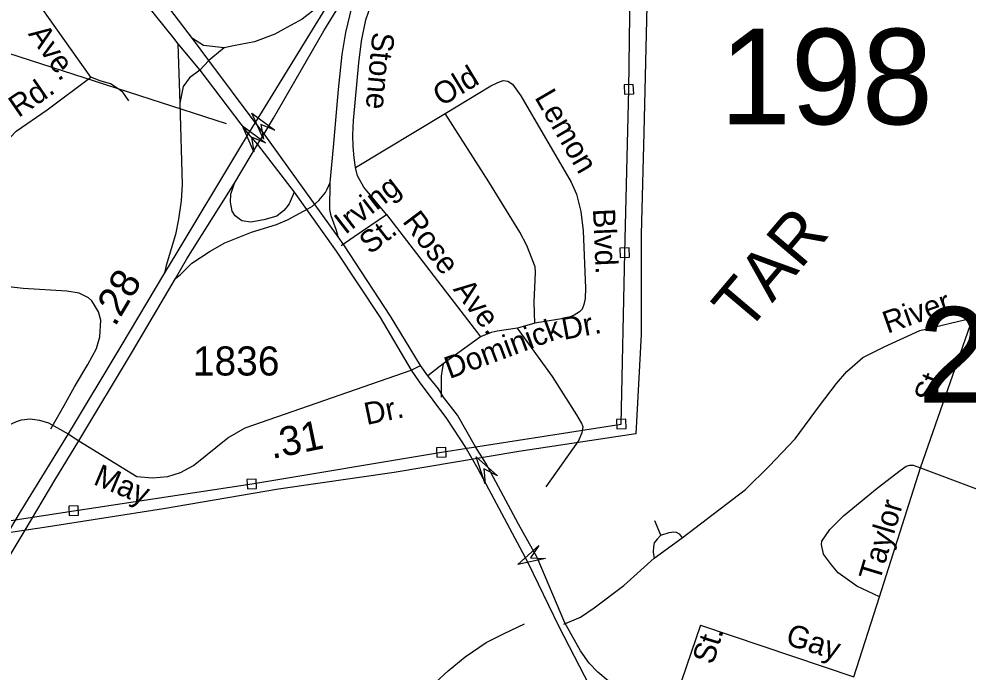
# Model space of a CAD drawing. Extents: x 2220236 to 2384410, y 720751 to 894131.
# Drawn here: x 2347083 to 2351158, y 803171 to 805976 of the extents above; entities that cross this region are included whole.
import ezdxf

# ---------------------------------------------------------------- set-up
doc = ezdxf.new("R2010")
doc.units = 0
doc.layers.add('Default', color=7, linetype='Continuous')

msp = doc.modelspace()

# ---------------------------------------------------------------- linework, layer by layer
at = {"layer": 'Default'}
for p, q in [((2347391.6, 805725.9), (2347153.6, 806062.9)), ((2347973.4, 805524.9), (2346818.6, 805898)), ((2347764.5, 805869.5), (2347773.7, 805614.1)), ((2347858.9, 805756.5), (2347898, 805797.6)), ((2348527.9, 805337.7), (2348913, 805570.3)), ((2348521.5, 805041.4), (2348660.2, 805136.4)), ((2348465.6, 805003.2), (2348521.5, 805041.4)), ((2349297.7, 804669.2), (2349224, 804648.2)), ((2350954.6, 804047.4), (2351178.8, 804691.8)), ((2349064.4, 804610.5), (2348903.9, 804494.5)), ((2348903.9, 804494.5), (2348891.6, 804484.9)), ((2348903.9, 804494.5), (2348900.5, 804470.8)), ((2348891.6, 804484.9), (2348838.1, 804443.4)), ((2350777.4, 803493.3), (2350954.6, 804047.4)), ((2350954.6, 804047.4), (2351393.8, 803882.9)), ((2349838.6, 803757.9), (2349813.8, 803819.8)), ((2349809.7, 803659.7), (2349930.6, 803747.1)), ((2350667.5, 803150.1), (2350777.4, 803493.3)), ((2350009.6, 803372.6), (2350667.5, 803150.1))]:
    msp.add_line(p, q, dxfattribs=at)
for points in [[(2346701.4, 803768.3), (2347318, 803863.7), (2348082.4, 803978.8), (2348896.4, 804114.6), (2349668.8, 804235.8), (2349684, 804971.7), (2349701.5, 805673.7), (2349709.8, 806313.5), (2349726.9, 807063.6), (2349743.4, 807839.6), (2349751, 808535.4), (2349765.4, 809335.3), (2349939.6, 809817.2), (2350090.8, 810226.9), (2350328.9, 810529.6), (2350606.6, 810882.8), (2351204.5, 811377.9), (2351739.2, 811798), (2352473.9, 812380.7), (2353111.5, 812908.3), (2353471.9, 813194.5), (2353662.4, 813640.7)], [(2346789.7, 807005.9), (2346852.6, 806975.9), (2346898.8, 806948.2), (2346934.3, 806923), (2347014.4, 806847.4), (2347298.8, 806482.4), (2347357.3, 806415), (2347516, 806189.4), (2347627.8, 806041), (2347745.7, 805894.2), (2347764.5, 805869.5)], [(2348097.3, 805531.4), (2347898, 805797.6), (2347827.8, 805891.8), (2347689.5, 806075.3), (2347566.8, 806231.4), (2347503.4, 806312.7), (2347415.8, 806431), (2347165, 806746.7), (2347090.6, 806843.8), (2347046, 806901.9)], [(2348527.9, 805337.7), (2348521.4, 805378.9), (2348518.2, 805427.7), (2348516.6, 805476.6), (2348519.4, 805539.8), (2348542.1, 805787.2), (2348553.1, 805880.9), (2348572.6, 805972.2), (2348584.7, 806010), (2348601.8, 806053.8), (2348654.1, 806161), (2348777.6, 806368)], [(2349785.5, 806336.4), (2349765.7, 805488.5), (2349755, 805050.7), (2349754.1, 804620.7), (2349731.3, 804194.5), (2349228.4, 804118.6), (2348693.6, 804028.1), (2348196.6, 803956.2), (2347703.8, 803872.3), (2347190.8, 803792.1), (2346700, 803718.2)], [(2348486.6, 806166.2), (2348368.7, 806029.5), (2348298.1, 805974.7), (2348220.3, 805931.9), (2348181.2, 805911.4), (2348093.5, 805878.2), (2348004.3, 805860.7), (2347963.2, 805852.7)], [(2348486.6, 806166.2), (2348353.1, 805948.7), (2348126.6, 805579.9), (2348097.3, 805531.4)], [(2348136.1, 805482.8), (2348176.2, 805549.9), (2348391.6, 805925.1), (2348557.7, 806195.7)], [(2348418.2, 805274), (2348432.6, 805425.5), (2348455.1, 805672.7), (2348470, 805824.1), (2348486.8, 805917.4), (2348511.7, 806025.3), (2348557.7, 806195.7)], [(2347963.2, 805852.7), (2347875, 805861.7), (2347827.8, 805891.8)], [(2347764.5, 805869.5), (2347858.9, 805756.5), (2348067.2, 805483.3)], [(2347963.2, 805852.7), (2347914.6, 805812.6), (2347898, 805797.6)], [(2347858.9, 805756.5), (2347815.3, 805723.4), (2347787.7, 805685.3), (2347773.7, 805614.1)], [(2346806.2, 804843.8), (2346835.3, 805016.7), (2346899.7, 805238.2), (2346923, 805294.4), (2346956.2, 805354.8), (2347001.5, 805421.2), (2347070.5, 805494.1), (2347203.5, 805585.8), (2347391.6, 805725.9)], [(2347554.9, 805623.9), (2347528.3, 805661.6), (2347504.2, 805679.3), (2347476, 805696.9), (2347431.9, 805710.3), (2347391.6, 805725.9)], [(2348913, 805570.3), (2349109.5, 805688.6), (2349139.3, 805703), (2349161.2, 805711.1), (2349181.3, 805709.5), (2349201.4, 805695.7), (2349238.1, 805646.2), (2349454.3, 805274.9), (2349477, 805223.2), (2349495.8, 805149.3), (2349504.9, 805065.5), (2349515.9, 804819.8), (2349514.3, 804775.7), (2349508.8, 804749.7), (2349501, 804729.6), (2349489.1, 804717.5), (2349467.2, 804703.2), (2349439.4, 804692.8), (2349297.7, 804669.2)], [(2349682.4, 805653), (2349722.3, 805654.6), (2349720.7, 805694.5), (2349680.8, 805692.9), (2349682.4, 805653)], [(2347773.7, 805614.1), (2347783, 805264.7), (2347778.6, 805194.4), (2347768.1, 805116.5), (2347754.9, 805050), (2347714.4, 804916.9), (2347707.5, 804886.2)], [(2349297.7, 804669.2), (2349294.7, 804759.2), (2349301.1, 804887.1), (2349298.9, 804911.2), (2349263.7, 805002.6), (2349233, 805060.4), (2349100.5, 805276.6), (2348913, 805570.3)], [(2348097.3, 805531.4), (2348075.8, 805497.2), (2348067.2, 805483.3)], [(2348136.1, 805482.8), (2348097.3, 805531.4)], [(2348067.2, 805483.3), (2348025.9, 805414.1), (2347761, 804973.3), (2347707.5, 804886.2)], [(2348067.2, 805483.3), (2348107, 805436.7)], [(2348107, 805436.7), (2348136.1, 805482.8)], [(2348807.2, 804487.2), (2348677.5, 804699.8), (2348477, 805005.6), (2348453, 805039.6), (2348136.1, 805482.8)], [(2347754.7, 804861.8), (2347803.7, 804945.1), (2348007.8, 805271.2), (2348107, 805436.7)], [(2348107, 805436.7), (2348264.4, 805232.1), (2348444.9, 804979), (2348633.4, 804693.8), (2348766.6, 804466.7)], [(2348660.2, 805136.4), (2348563, 805254.1), (2348536.4, 805301.8), (2348527.9, 805337.7)], [(2348264.4, 805232.1), (2348242.9, 805182), (2348229.1, 805162.9), (2348220.4, 805152.8), (2348190.2, 805129.6), (2348133.4, 805112.5), (2348078.2, 805103.6), (2348040.1, 805109.3), (2348010.9, 805130.4), (2347998.6, 805149.7), (2347990.7, 805189), (2347991.7, 805224.1), (2348007.8, 805271.2)], [(2348343.2, 805172.3), (2348370.2, 805195.6), (2348398.2, 805230.8), (2348405.4, 805244.4), (2348418.2, 805274)], [(2348453, 805039.6), (2348445.4, 805066.7), (2348423.8, 805129.9), (2348417.8, 805156.9), (2348418.2, 805274)], [(2347754.7, 804861.8), (2347775.9, 804878.8), (2347824.7, 804926.6), (2347904.3, 804978.3), (2347966.1, 805015), (2348081.5, 805060.4), (2348189, 805093.8), (2348235.8, 805113.1), (2348303.7, 805149.9)], [(2348303.7, 805149.9), (2348323, 805160.4), (2348343.2, 805172.3)], [(2348660.2, 805136.4), (2349052.3, 804628.2), (2349064.4, 804610.5)], [(2349664.8, 804950.9), (2349704.8, 804952.6), (2349703.1, 804992.5), (2349663.2, 804990.9), (2349664.8, 804950.9)], [(2347707.5, 804886.2), (2347520, 804570.8), (2347293.3, 804194.6)], [(2347338.9, 804163.5), (2347569.7, 804547.1), (2347754.7, 804861.8)], [(2347219.5, 804215.2), (2347276.2, 804316.1), (2347321.4, 804396), (2347378.1, 804491.6), (2347415.9, 804560.9), (2347429.8, 804610.8), (2347433.7, 804681.8), (2347424.3, 804717.5), (2347406.4, 804745.9), (2347394.9, 804765.8), (2347381.1, 804778.1), (2347340.9, 804797.6), (2347288.7, 804806.9), (2347100.7, 804818.6), (2346925.1, 804837.8), (2346806.2, 804843.8)], [(2349930.6, 803747.1), (2350201.9, 803954.2), (2350304.8, 804055.5), (2350415.4, 804172.2), (2350519.7, 804314.2), (2350593.3, 804410.1), (2350637.8, 804461.4), (2350706.9, 804522.3), (2350798.4, 804567.2), (2350951.6, 804637.1), (2351178.8, 804691.8)], [(2349224, 804648.2), (2349136.1, 804635.2), (2349110.3, 804629), (2349064.4, 804610.5)], [(2349346.1, 803965.9), (2349485.7, 804161.7), (2349501.2, 804199.8), (2349505, 804223.9), (2349498.7, 804241.7), (2349478.3, 804275.5), (2349374.3, 804440.3), (2349224, 804648.2)], [(2347338.9, 804163.5), (2347588.6, 804010.3), (2347656.3, 804005.1), (2347721.3, 804010.3), (2347776.1, 804027.4), (2347832.5, 804058.2), (2347979.6, 804176.3), (2348054, 804219.9), (2348766.6, 804466.7)], [(2348766.6, 804466.7), (2348807.2, 804487.2)], [(2348766.6, 804466.7), (2348801.5, 804417), (2348919.1, 804259.7), (2349003.3, 804131.4), (2349053.4, 804043.1)], [(2349087, 804067.2), (2349043.4, 804137.4), (2348965.2, 804274.7), (2348906.2, 804352), (2348884, 804387.2), (2348838.1, 804443.4), (2348807.2, 804487.2)], [(2348900.5, 804470.8), (2348896.2, 804441.5), (2348895.4, 804407.1), (2348895.4, 804360.7), (2348896, 804351.6)], [(2345461.4, 803059.4), (2345555.9, 803137.4), (2345679.1, 803223), (2345853.5, 803353.1), (2345934.8, 803393.3), (2345940.3, 803396.2), (2346148.6, 803487.4), (2346346.1, 803608.1), (2346484.7, 803712.5), (2346767.8, 803971.8), (2346960.1, 804172.2), (2347035.4, 804229.4), (2347072, 804246.8), (2347093.5, 804253.5), (2347130.1, 804257.9), (2347170.1, 804252.4), (2347210, 804241.3), (2347293.3, 804194.6)], [(2349649.6, 804215), (2349689.6, 804216.6), (2349687.9, 804256.6), (2349648, 804255), (2349649.6, 804215)], [(2347293.3, 804194.6), (2347087.3, 803859.3), (2346958, 803640.5), (2346878, 803500.6), (2346829.7, 803409.6), (2346776.4, 803297.4), (2346740.9, 803205.3), (2346706.5, 803098.7), (2346678.2, 802989.8), (2346635.4, 802764.4), (2346581, 802475.7), (2346543.4, 802235.3), (2346526.5, 802118.8), (2346519, 802043.6), (2346511.5, 801961), (2346505.9, 801793.7), (2346494.6, 801474.3), (2346460.8, 800446.4), (2346440.1, 799717.3), (2346423.3, 798959.5), (2346418.3, 798634.2), (2346404, 798402.2)], [(2347293.3, 804194.6), (2347338.9, 804163.5)], [(2346475.7, 798398.2), (2346496.3, 798954.6), (2346513.4, 799715.4), (2346530.3, 800457.7), (2346567.8, 801476.1), (2346575.4, 801778.7), (2346586.6, 802023), (2346590.4, 802101.9), (2346607.3, 802246.6), (2346633.7, 802436.9), (2346668.2, 802656.7), (2346719.2, 802916.6), (2346742, 803019.8), (2346775.3, 803129.8), (2346808.6, 803215.3), (2346849.2, 803326.3), (2346910.2, 803445.1), (2346986.9, 803579.5), (2347109.6, 803780.5), (2347236.7, 803994.8), (2347338.9, 804163.5)], [(2348877.2, 804093.8), (2348917.2, 804095.5), (2348915.6, 804135.4), (2348875.6, 804133.8), (2348877.2, 804093.8)], [(2349053.4, 804043.1), (2349267.3, 803641.4)], [(2349307.3, 803662.3), (2349228.1, 803805.2), (2349087, 804067.2)], [(2350777.4, 803493.3), (2350680.8, 803540.2), (2350600.2, 803597.2), (2350571.7, 803630.8), (2350537.2, 803676.4), (2350528.7, 803718.3), (2350530.5, 803732.4), (2350563.9, 803782.8), (2350623.3, 803841.4), (2350767.7, 803961.1), (2350866.8, 804036.2), (2350892.5, 804054.7), (2350908.5, 804058.7), (2350922.5, 804058.9), (2350954.6, 804047.4)], [(2348063.2, 803958), (2348103.2, 803959.6), (2348101.6, 803999.5), (2348061.6, 803997.9), (2348063.2, 803958)], [(2347298.8, 803842.9), (2347338.8, 803844.6), (2347337.1, 803884.5), (2347297.2, 803882.9), (2347298.8, 803842.9)], [(2349838.6, 803757.9), (2349822.6, 803741.9), (2349810.9, 803725.8), (2349807.1, 803709.6), (2349805.4, 803683.6), (2349809.7, 803659.7)], [(2349838.6, 803757.9), (2349874.3, 803770.4), (2349894.2, 803772.6), (2349904.3, 803770.8), (2349918.3, 803765), (2349930.6, 803747.1)], [(2349267.3, 803641.4), (2349400.4, 803366.3), (2349554.2, 803070.5), (2349765.2, 802659.7), (2349855.7, 802482.8), (2349901.4, 802391.5), (2349944.2, 802302.5), (2349968.5, 802267.5), (2349989.8, 802240.6), (2350017.2, 802212.7), (2350073.5, 802162.9), (2350139.2, 802136.6), (2350215.8, 802112.5), (2350324.2, 802087.3), (2350753.3, 801936.1), (2351199.9, 801789.4)], [(2355867.9, 801058.1), (2355433.3, 801194.2), (2355005.8, 801339), (2354686.5, 801445.1), (2354532, 801497.3), (2354233, 801591.6), (2353731.1, 801759.6), (2353201.2, 801935), (2352868, 802047.1), (2352538.9, 802151.1), (2351878.4, 802371), (2351433, 802506.8), (2350991.9, 802650.3), (2350559.5, 802789.4), (2349666.5, 803100.7), (2349612.9, 803132.7), (2349568.5, 803170.3), (2349530.8, 803209.1), (2349493.2, 803261.6), (2349427.1, 803382.5), (2349307.3, 803662.3)], [(2349422.3, 803375.7), (2349494.3, 803406.9), (2349553.1, 803446.5), (2349680.3, 803542.6), (2349809.7, 803659.7)], [(2348912.6, 802275.3), (2348844, 802324.6), (2348805.7, 802356), (2348766.9, 802415.6), (2348746.3, 802463.2), (2348731.7, 802523.1), (2348728.8, 802593.2), (2348735.5, 802693.1), (2348756.1, 802821.4), (2348775.2, 802903.6), (2348788.2, 802975.7), (2348817.5, 803038), (2348838.8, 803084.3), (2348872.3, 803126.6), (2348925.7, 803175.2), (2348999.1, 803236.1), (2349088.2, 803297.1), (2349165.7, 803336.1), (2349253.2, 803377.1)], [(2350009.6, 803372.6), (2349765.9, 802659.5)]]:
    msp.add_lwpolyline(points, dxfattribs=at)
for points in [[(2348132.3, 805459.3), (2348082.6, 805570.7), (2348181.3, 805499), (2348121, 805523.3)], [(2348091.7, 805404.6), (2348043.1, 805516.4), (2348141.1, 805443.9), (2348081.1, 805468.7)], [(2349084.7, 803979), (2349045.5, 804094.4), (2349137.2, 804014), (2349079.4, 804043.8)], [(2349344.2, 803658.7), (2349225, 803632.8), (2349315.2, 803714.8), (2349279.2, 803660.7)]]:
    msp.add_lwpolyline(points, close=True, dxfattribs=at)

# ---------------------------------------------------------------- texts
for s, height, rotation, p in [('Ave.', 95, 305.2307, (2347119.8, 805911.5)), ('Stone', 95, 264.9352, (2348600.9, 805922.6)), ('Old', 95, 31.1316, (2348896.7, 805598.2)), ('Rd.', 95, 34.5863, (2347080.5, 805549.8)), ('Lemon', 95, 300.2115, (2349294.5, 805639.4)), ('Irving', 95, 37.7042, (2348483.6, 805047.4)), ('Rose', 95, 306.9074, (2348726.3, 805106.3)), ('Blvd.', 95, 272.5636, (2349547.1, 805160)), ('TAR', 210, 49.7715, (2350206, 804622.4)), ('St.', 95, 37.9854, (2348590.8, 804961.9)), ('.28', 125, 59.2653, (2347494.8, 804650.8)), ('Ave.', 95, 307.2214, (2348944.2, 804814.1)), ('River', 95, 19.4463, (2350811.9, 804623.9)), ('Dr.', 95, 10.5667, (2349422.3, 804597.3)), ('Dominick', 95, 20.3425, (2348931.2, 804428.8)), ('St.', 95, 69.2941, (2351010.8, 804319.6)), ('Dr.', 95, 11.6889, (2348575.7, 804231.7)), ('.31', 125, 11.6889, (2348169.4, 804085.5)), ('May', 95, 337.3605, (2347397.4, 803978.7)), ('Taylor', 95, 73.2126, (2350778.3, 803555.7)), ('Gay', 95, 342.3341, (2350369.9, 803290.8)), ('St.', 95, 72.7468, (2350063.1, 803199.3))]:
    msp.add_text(s, height=height, rotation=rotation, dxfattribs=at).set_placement(p)
for s, height, p in [('198', 410.1, (2350092.1, 805523.6)), ('205', 410.1, (2350943.1, 804328)), ('1836', 125, (2347829.3, 804444.4))]:
    msp.add_text(s, height=height, dxfattribs=at).set_placement(p)

doc.saveas('drawing.dxf')
